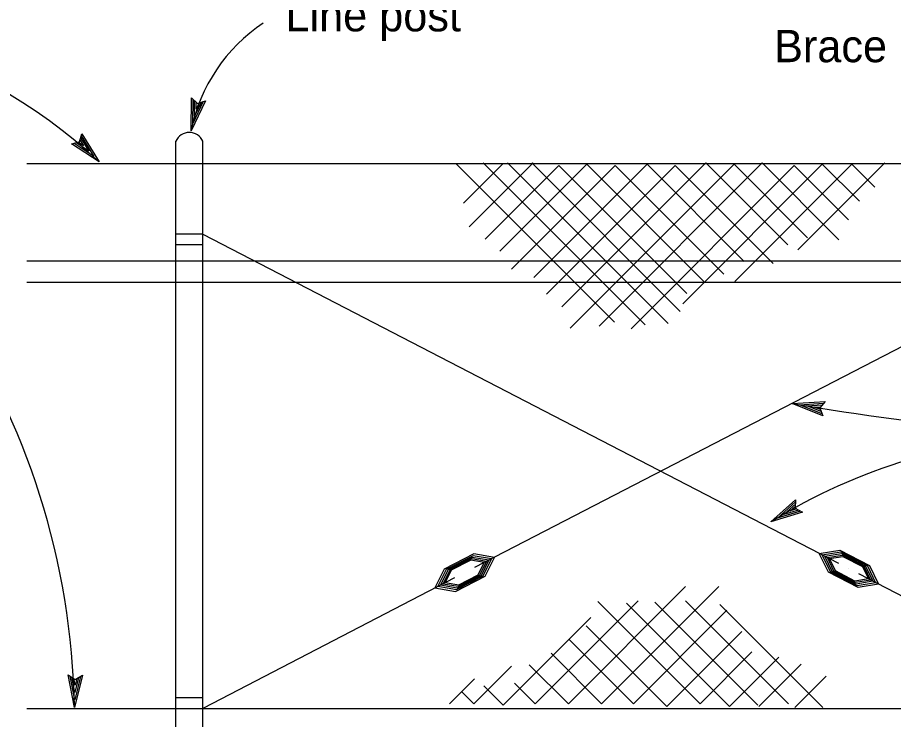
# Model space of a CAD drawing. Extents: x 6710407 to 6714861, y 1868090 to 1871317.
# Drawn here: x 6712138.9 to 6712301.4, y 1870371.8 to 1870501.9 of the extents above; entities that cross this region are included whole.
import ezdxf

# ---------------------------------------------------------------- set-up
doc = ezdxf.new("R2010")
doc.units = 0
for name, color, linetype in [('G-MARK', 7, 'Continuous'), ('G-TEXT', 7, 'Continuous'), ('Nongeo Data(60)', 7, 'Continuous')]:
    doc.layers.add(name, color=color, linetype=linetype)

msp = doc.modelspace()

# ---------------------------------------------------------------- linework, layer by layer
at = {"layer": 'G-MARK'}
for centre, radius, start, end in [((6712088.09, 1870404.51), 96.65, 46.9468, 103.018), ((6712201.68, 1870474.88), 31.13, 123.4429, 168.8431), ((6712010.63, 1870371.44), 138.89, 1.0544, 66.3616), ((6712376.9, 1870992.22), 569.72, 260.5099, 268.0518), ((6712334.58, 1870318.41), 105.92, 91.4112, 121.8505)]:
    msp.add_arc(centre, radius, start, end, dxfattribs=at)
msp.add_open_spline([(6712330.22, 1870486.07), (6712330.22, 1870508.45), (6712306.44, 1870522.83), (6712297.09, 1870524.27), (6712290.26, 1870524.63), (6712278.4, 1870524.63)], degree=2, dxfattribs=at)
at = {"layer": 'G-TEXT'}
for p, q in [((6712171.14, 1870480.9), (6712171.18, 1870487.04)), ((6712173.78, 1870486.45), (6712171.14, 1870480.9)), ((6712171.18, 1870487.04), (6712171.18, 1870487.04)), ((6712171.18, 1870487.04), (6712172.3, 1870485.97)), ((6712171.45, 1870482.26), (6712171.48, 1870486.74)), ((6712173.39, 1870486.32), (6712171.45, 1870482.24)), ((6712171.76, 1870483.59), (6712171.78, 1870486.49)), ((6712172.3, 1870485.97), (6712173.78, 1870486.45)), ((6712173.78, 1870486.45), (6712173.78, 1870486.45)), ((6712172.99, 1870486.17), (6712171.76, 1870483.59)), ((6712172.07, 1870484.94), (6712172.08, 1870486.18)), ((6712172.61, 1870486.08), (6712172.07, 1870484.94)), ((6712150.45, 1870478.86), (6712150.85, 1870480.37)), ((6712150.75, 1870479.97), (6712153.11, 1870476.13)), ((6712150.85, 1870480.37), (6712150.85, 1870480.37)), ((6712150.85, 1870480.37), (6712154.07, 1870475.14)), ((6712171.14, 1870480.9), (6712171.14, 1870480.9)), ((6712148.94, 1870478.51), (6712150.45, 1870478.86)), ((6712154.07, 1870475.14), (6712148.94, 1870478.51)), ((6712148.94, 1870478.51), (6712148.94, 1870478.51)), ((6712153.1, 1870476.13), (6712149.36, 1870478.59)), ((6712152.15, 1870477.12), (6712149.73, 1870478.71)), ((6712151.19, 1870478.11), (6712150.15, 1870478.79)), ((6712150.53, 1870479.18), (6712151.19, 1870478.11)), ((6712150.65, 1870479.55), (6712152.15, 1870477.12)), ((6712154.07, 1870475.14), (6712154.07, 1870475.14)), ((6712282.63, 1870430.34), (6712288.76, 1870430.7)), ((6712288.34, 1870428.07), (6712282.63, 1870430.34)), ((6712282.63, 1870430.34), (6712282.63, 1870430.34)), ((6712288.18, 1870428.45), (6712283.99, 1870430.12)), ((6712284, 1870430.12), (6712288.48, 1870430.39)), ((6712285.36, 1870429.9), (6712288.24, 1870430.07)), ((6712288.01, 1870428.84), (6712285.36, 1870429.9)), ((6712286.72, 1870429.68), (6712287.96, 1870429.75)), ((6712287.89, 1870429.22), (6712286.72, 1870429.68)), ((6712288.76, 1870430.7), (6712287.76, 1870429.52)), ((6712287.76, 1870429.52), (6712288.34, 1870428.07)), ((6712288.76, 1870430.7), (6712288.76, 1870430.7)), ((6712288.34, 1870428.07), (6712288.34, 1870428.07)), ((6712278.69, 1870408.38), (6712283.26, 1870412.5)), ((6712279.9, 1870409.07), (6712283.23, 1870412.07)), ((6712281.1, 1870409.74), (6712283.25, 1870411.68)), ((6712283.26, 1870412.5), (6712283.22, 1870410.94)), ((6712283.26, 1870412.5), (6712283.26, 1870412.5)), ((6712284.57, 1870410.17), (6712278.69, 1870408.38)), ((6712284.21, 1870410.38), (6712279.89, 1870409.06)), ((6712283.83, 1870410.57), (6712281.1, 1870409.74)), ((6712282.3, 1870410.42), (6712283.22, 1870411.25)), ((6712283.5, 1870410.79), (6712282.3, 1870410.42)), ((6712283.22, 1870410.94), (6712284.57, 1870410.17)), ((6712284.57, 1870410.17), (6712284.57, 1870410.17)), ((6712278.69, 1870408.38), (6712278.69, 1870408.38)), ((6712149.5, 1870374), (6712148.32, 1870380.03)), ((6712148.32, 1870380.03), (6712148.32, 1870380.03)), ((6712148.32, 1870380.03), (6712149.63, 1870379.2)), ((6712149.53, 1870375.39), (6712148.67, 1870379.78)), ((6712149.57, 1870376.76), (6712149.01, 1870379.6)), ((6712149.6, 1870378.14), (6712149.36, 1870379.35)), ((6712150.98, 1870379.96), (6712149.5, 1870374)), ((6712150.62, 1870379.75), (6712149.53, 1870375.38)), ((6712150.26, 1870379.53), (6712149.57, 1870376.76)), ((6712149.91, 1870379.36), (6712149.6, 1870378.14)), ((6712149.63, 1870379.2), (6712150.98, 1870379.96)), ((6712150.98, 1870379.96), (6712150.98, 1870379.96)), ((6712149.5, 1870374), (6712149.5, 1870374))]:
    msp.add_line(p, q, dxfattribs=at)
at = {"layer": 'Nongeo Data(60)'}
for p, q in [((6712168.3, 1870324.76), (6712168.3, 1870478.96)), ((6712173.3, 1870324.76), (6712173.3, 1870478.96)), ((6712222.73, 1870463.08), (6712234.6, 1870474.95)), ((6712255.36, 1870444.92), (6712225.34, 1870474.95)), ((6712259.63, 1870445.16), (6712229.85, 1870474.95)), ((6712261.89, 1870447.42), (6712234.36, 1870474.95)), ((6712239.94, 1870448.25), (6712266.64, 1870474.95)), ((6712246.82, 1870444.69), (6712277.08, 1870474.95)), ((6712281.83, 1870459.76), (6712266.64, 1870474.95)), ((6712291.32, 1870460.71), (6712277.08, 1870474.95)), ((6712283.72, 1870458.81), (6712299.86, 1870474.95)), ((6712173.39, 1870474.76), (6712140.63, 1870474.76)), ((6712348.65, 1870474.76), (6712173.39, 1870474.76)), ((6712249.67, 1870445.4), (6712220.36, 1870474.71)), ((6712221.66, 1870467.47), (6712228.9, 1870474.71)), ((6712225.7, 1870460.82), (6712239.34, 1870474.47)), ((6712228.43, 1870458.57), (6712244.56, 1870474.71)), ((6712230.56, 1870455.25), (6712249.79, 1870474.47)), ((6712234.71, 1870453.7), (6712255.72, 1870474.71)), ((6712237.09, 1870450.62), (6712260.94, 1870474.47)), ((6712263.08, 1870450.74), (6712239.34, 1870474.47)), ((6712241.48, 1870444.33), (6712271.86, 1870474.71)), ((6712266.28, 1870452.99), (6712244.56, 1870474.71)), ((6712269.96, 1870454.3), (6712249.79, 1870474.47)), ((6712252.75, 1870444.21), (6712283.01, 1870474.47)), ((6712273.76, 1870456.67), (6712255.72, 1870474.71)), ((6712279.1, 1870456.31), (6712260.94, 1870474.47)), ((6712262.36, 1870448.84), (6712288.23, 1870474.71)), ((6712285.5, 1870461.06), (6712271.86, 1870474.71)), ((6712271.98, 1870452.99), (6712293.69, 1870474.71)), ((6712293.1, 1870464.38), (6712283.01, 1870474.47)), ((6712295.12, 1870467.83), (6712288.23, 1870474.71)), ((6712297.96, 1870470.44), (6712293.69, 1870474.71)), ((6712173.3, 1870461.76), (6712168.3, 1870461.76)), ((6712173.3, 1870461.76), (6712291.25, 1870400.77)), ((6712343.3, 1870461.76), (6712223.71, 1870399.92)), ((6712173.3, 1870459.76), (6712168.3, 1870459.76)), ((6712348.3, 1870456.76), (6712140.63, 1870456.76)), ((6712348.3, 1870452.76), (6712140.63, 1870452.76)), ((6712223.6, 1870402.46), (6712218.08, 1870399.64)), ((6712223.43, 1870402.11), (6712218.46, 1870399.58)), ((6712223.28, 1870401.8), (6712218.81, 1870399.52)), ((6712226.37, 1870401.27), (6712223.28, 1870401.8)), ((6712226.86, 1870401.52), (6712223.43, 1870402.11)), ((6712227.41, 1870401.8), (6712223.6, 1870402.46)), ((6712225.7, 1870398.34), (6712227.41, 1870401.8)), ((6712287.68, 1870402.56), (6712291.49, 1870403.18)), ((6712289.36, 1870399.08), (6712287.68, 1870402.56)), ((6712288.23, 1870402.28), (6712291.66, 1870402.83)), ((6712289.74, 1870399.14), (6712288.23, 1870402.28)), ((6712288.72, 1870402.02), (6712291.81, 1870402.52)), ((6712290.08, 1870399.2), (6712288.72, 1870402.02)), ((6712289.17, 1870401.79), (6712291.95, 1870402.24)), ((6712290.39, 1870399.25), (6712289.17, 1870401.79)), ((6712289.57, 1870401.58), (6712292.07, 1870401.99)), ((6712291.49, 1870403.18), (6712296.99, 1870400.32)), ((6712291.66, 1870402.83), (6712296.61, 1870400.26)), ((6712291.81, 1870402.52), (6712296.27, 1870400.2)), ((6712291.95, 1870402.24), (6712295.96, 1870400.16)), ((6712292.07, 1870401.99), (6712295.68, 1870400.11)), ((6712223.15, 1870401.52), (6712219.12, 1870399.47)), ((6712223.03, 1870401.27), (6712219.4, 1870399.42)), ((6712225.53, 1870400.84), (6712223.03, 1870401.27)), ((6712225.93, 1870401.05), (6712223.15, 1870401.52)), ((6712224.4, 1870398.57), (6712225.53, 1870400.84)), ((6712224.68, 1870398.52), (6712225.93, 1870401.05)), ((6712224.98, 1870398.46), (6712226.37, 1870401.27)), ((6712225.32, 1870398.4), (6712226.86, 1870401.52)), ((6712290.67, 1870399.3), (6712289.57, 1870401.58)), ((6712295.68, 1870400.11), (6712296.78, 1870397.83)), ((6712295.96, 1870400.16), (6712297.18, 1870397.62)), ((6712296.27, 1870400.2), (6712297.63, 1870397.38)), ((6712296.61, 1870400.26), (6712298.12, 1870397.12)), ((6712296.99, 1870400.32), (6712298.67, 1870396.84)), ((6712218.08, 1870399.64), (6712216.37, 1870396.17)), ((6712218.46, 1870399.58), (6712216.92, 1870396.46)), ((6712218.81, 1870399.52), (6712217.42, 1870396.71)), ((6712219.12, 1870399.47), (6712217.87, 1870396.94)), ((6712219.4, 1870399.42), (6712218.28, 1870397.15)), ((6712220.51, 1870396.18), (6712224.98, 1870398.46)), ((6712220.65, 1870396.47), (6712224.68, 1870398.52)), ((6712220.78, 1870396.72), (6712224.4, 1870398.57)), ((6712294.86, 1870396.22), (6712289.36, 1870399.08)), ((6712294.69, 1870396.57), (6712289.74, 1870399.14)), ((6712294.54, 1870396.88), (6712290.08, 1870399.2)), ((6712294.4, 1870397.17), (6712290.39, 1870399.25)), ((6712294.28, 1870397.42), (6712290.67, 1870399.3)), ((6712293.17, 1870399.71), (6712293.17, 1870399.71)), ((6712293.17, 1870399.7), (6712293.17, 1870399.7)), ((6712293.17, 1870399.7), (6712293.17, 1870399.7)), ((6712293.17, 1870399.7), (6712293.17, 1870399.7)), ((6712293.18, 1870399.7), (6712293.18, 1870399.7)), ((6712294.98, 1870398.84), (6712343.34, 1870373.74)), ((6712220.02, 1870398.01), (6712173.4, 1870373.89)), ((6712217.87, 1870396.94), (6712220.65, 1870396.47)), ((6712218.28, 1870397.15), (6712220.78, 1870396.72)), ((6712220.18, 1870395.52), (6712225.7, 1870398.34)), ((6712220.35, 1870395.87), (6712225.32, 1870398.4)), ((6712296.78, 1870397.83), (6712294.28, 1870397.42)), ((6712297.18, 1870397.62), (6712294.4, 1870397.17)), ((6712297.63, 1870397.38), (6712294.54, 1870396.88)), ((6712298.12, 1870397.12), (6712294.69, 1870396.57)), ((6712298.67, 1870396.84), (6712294.86, 1870396.22)), ((6712216.37, 1870396.17), (6712220.18, 1870395.52)), ((6712216.92, 1870396.46), (6712220.35, 1870395.87)), ((6712217.42, 1870396.71), (6712220.51, 1870396.18)), ((6712241.12, 1870374.67), (6712262.84, 1870396.39)), ((6712247.29, 1870374.67), (6712269.01, 1870396.39)), ((6712234.95, 1870374.67), (6712254.06, 1870393.78)), ((6712265.57, 1870374.67), (6712246.58, 1870393.66)), ((6712281.94, 1870374.67), (6712262.84, 1870393.78)), ((6712271.03, 1870374.2), (6712251.92, 1870393.3)), ((6712253.23, 1870374.67), (6712270.55, 1870392)), ((6712276.25, 1870374.44), (6712257.14, 1870393.54)), ((6712288.35, 1870373.96), (6712269.25, 1870393.07)), ((6712229.02, 1870374.44), (6712245.28, 1870390.69)), ((6712259.4, 1870374.2), (6712244.45, 1870389.15)), ((6712259.4, 1870374.2), (6712273.28, 1870388.08)), ((6712253.23, 1870374.67), (6712241.24, 1870386.66)), ((6712247.29, 1870374.67), (6712237.92, 1870384.05)), ((6712265.57, 1870374.67), (6712275.18, 1870384.28)), ((6712271.03, 1870374.2), (6712280.16, 1870383.34)), ((6712223.56, 1870374.67), (6712230.56, 1870381.67)), ((6712241.12, 1870374.67), (6712233.88, 1870381.91)), ((6712276.49, 1870374.2), (6712284.32, 1870382.03)), ((6712219.05, 1870374.67), (6712223.68, 1870379.3)), ((6712283.13, 1870373.96), (6712288.95, 1870379.77)), ((6712229.02, 1870374.44), (6712225.46, 1870378)), ((6712234.95, 1870374.67), (6712231.15, 1870378.47)), ((6712173.3, 1870375.76), (6712168.3, 1870375.76)), ((6712223.56, 1870374.67), (6712221.42, 1870376.81)), ((6712176.07, 1870373.76), (6712140.63, 1870373.76)), ((6712348.3, 1870373.76), (6712176.07, 1870373.76))]:
    msp.add_line(p, q, dxfattribs=at)
msp.add_arc((6712170.8, 1870477.88), 2.72, 23.2888, 156.7112, dxfattribs=at)

# ---------------------------------------------------------------- texts
for s, p in [('Line post', (6712188.63, 1870499.34)), ('Brace', (6712279.29, 1870493.62))]:
    msp.add_text(s, height=6, dxfattribs=at).set_placement(p)

doc.saveas('drawing.dxf')
